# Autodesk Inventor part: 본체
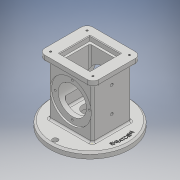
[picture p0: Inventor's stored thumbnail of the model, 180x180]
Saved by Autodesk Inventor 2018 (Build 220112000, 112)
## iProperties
Created: 2019-08
Part Number: 본체
Material: 일반
Document SubType Name: Modeling
Designer: USER
Density: 1 g/cm^3
Appearance: 기본값
Mass: 384.774 g
Surface Area: 783.555 cm^2
Volume: 384.774 cm^3
Author: USER
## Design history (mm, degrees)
sketch "스케치2"
  geometry: L1 (0, 66)-(74, 66); L2 (74, 66)-(74, 0); L3 (74, 0)-(0, 0); L4 (0, 0)-(0, 66); 1 further point
  constraints: 8 end point, 2 parallel, 1 coincident, 1 horizontal, 1 perpendicular
  dimensions: "d2" = 74 distance of L1.start L1.end; "d3" = 66 distance of L1.end L2.end
extrude "돌출1" new body sketch "스케치2" distance "d4" = 88; taper "d5" = 0 deg
node "작업 평면1"
node "작업 평면2"
sketch "스케치3"
  geometry: 1 further point
sketch "스케치4"
  geometry: L1 (0, 66)-(74, 66) reference; L2 (74, 66)-(74, 0) reference; L3 (74, 0)-(0, 0) reference; L4 (0, 0)-(0, 66) reference; C1 r 67.5 at (37, 33); 3 further points
  constraints: 2 midpoint, 1 centre point, 1 horizontal alignment, 1 vertical alignment
  dimensions: "d8" = 135 diameter of C1
extrude "돌출2" join sketch "스케치4" distance "d9" = 10; taper "d10" = 0 deg
node "작업 평면3"
sketch "스케치5"
  geometry: L1 (-9, 74)-(83, 74); L2 (83, 74)-(83, -8); L3 (83, -8)-(-9, -8); L4 (-9, -8)-(-9, 74); L5 (74, 66)-(0, 66) reference; L6 (0, 66)-(0, 0) reference; L7 (0, 0)-(74, 0) reference; L8 (74, 0)-(74, 66) reference; 5 further points
  constraints: 8 end point, 4 midpoint, 2 parallel, 1 horizontal, 1 horizontal alignment, 1 perpendicular, 1 vertical alignment
  dimensions: "d12" = 92 distance of L1.start L1.end; "d13" = 82 distance of L1.end L2.end
extrude "돌출3" join sketch "스케치5" distance "d14" = 10; taper "d15" = 0 deg
sketch "스케치6"
  geometry: L1 (-9, 74)-(83, 74) reference; L2 (-9, -8)-(-9, 74) reference; L3 (83, -8)-(-9, -8) reference; L4 (83, 74)-(83, -8) reference; L5 (11, 59)-(63, 59); L6 (63, 59)-(63, 7); L7 (63, 7)-(11, 7); L8 (11, 7)-(11, 59); 5 further points
  constraints: 8 end point, 4 midpoint, 2 parallel, 1 horizontal, 1 horizontal alignment, 1 perpendicular, 1 vertical alignment
  dimensions: "d16" = 52 distance of L5.start L5.end; "d17" = 52 distance of L5.end L6.end
extrude "돌출4" cut sketch "스케치6" distance "d18" = 8; taper "d19" = 0 deg
sketch "스케치7"
  geometry: L1 (74, 0)-(0, 0) reference; L2 (74, 0)-(74, 88) reference; L3 (0, 88)-(74, 88) reference; L4 (0, 0)-(0, 88) reference; L5 (-30.5, -10)-(104.5, -10) reference; L6 (83, 88)-(-9, 88) reference; C1 r 35 at (37, 44); 2 further points
  constraints: 1 centre point, 1 midpoint, 1 vertical alignment
  dimensions: "d20" = 70 diameter of C1; "d21" = 54 distance from line of L5 C1.centre
extrude "돌출5" cut sketch "스케치7" distance "d22" = 3; taper "d23" = 0 deg
sketch "스케치8"
  geometry: C1 r 35 at (0, 0) reference; C2 r 24 at (0, 0); 1 further point
  constraints: 1 centre point, 1 coincident
  dimensions: "d24" = 48 diameter of C2
extrude "돌출6" cut sketch "스케치8" distance "d25" = 8; taper "d26" = 0 deg
sketch "스케치9"
  geometry: C1 r 67.5 at (0, 0) reference; C2 r 25 at (0, 0); 1 further point
  constraints: 1 centre point, 1 coincident
  dimensions: "d27" = 50 diameter of C2
extrude "돌출7" cut sketch "스케치9" distance "d28" = 18; taper "d29" = 0 deg
sketch "스케치10"
  geometry: C1 r 25 at (0, 0) reference; C2 r 12.5 at (0, 0); 1 further point
  constraints: 1 centre point, 1 coincident
  dimensions: "d30" = 25 diameter of C2
extrude "돌출8" cut sketch "스케치10" distance "d31" = 10; taper "d32" = 0 deg
node "작업 평면4"
sketch "스케치11"
  geometry: L1 (15, 11)-(59, 11); L2 (59, 11)-(59, 55); L3 (59, 55)-(15, 55); L4 (15, 55)-(15, 11); L5 (11, 59)-(63, 59) reference; L6 (11, 7)-(11, 59) reference; L7 (63, 7)-(11, 7) reference; L8 (63, 59)-(63, 7) reference; L9 (11, 59)-(63, 59) reference; L10 (11, 7)-(11, 59) reference; 5 further points
  constraints: 8 end point, 4 midpoint, 2 parallel, 1 horizontal, 1 horizontal alignment, 1 perpendicular, 1 vertical alignment
  dimensions: "d34" = 44 distance of L3.end L1.start; "d35" = 44 distance of L2.end L3.end
extrude "돌출9" cut sketch "스케치11" distance "d36" = 74; taper "d37" = 0 deg
sketch "스케치12"
  geometry: C1 r 25 at (0, 0) reference; C2 r 67.5 at (0, 0) reference; 4 further points
  constraints: 2 vertical alignment, 1 horizontal alignment
  dimensions: "d38" = 59 distance of C1.centre point (0, 59); "d39" = 59 distance of point (-59, 0) C1.centre; "d40" = 59 distance of C1.centre point (0, -59)
hole "구멍1" sketch "스케치12" at (-59, 0), (0, -59), (0, 59) diameter "d41" = 9; stored, may be unused: countersink angle "d45" = 90 deg, drill point angle "d47" = 118 deg; dims "d42" = 6, "d43" = 4, "d44" = 2, "d46" = 8
sketch "스케치13"
  geometry: L1 (11, 7)-(11, 59) reference; L2 (11, 59)-(63, 59) reference; L3 (63, 59)-(63, 7) reference; L4 (63, 7)-(11, 7) reference; L5 (-9, 74)-(83, 74) reference; L6 (-9, -8)-(-9, 74) reference; L7 (83, -8)-(-9, -8) reference; L8 (83, 74)-(83, -8) reference; 5 further points
  constraints: 2 horizontal alignment, 2 vertical alignment
  dimensions: "d48" = 10 distance from line of L6 point (1, 64); "d49" = 10 distance from line of L5 point (1, 64); "d53" = 10 distance from line of L7 point (73, 2); "d54" = 10 distance from line of L8 point (73, 2)
hole "구멍2" sketch "스케치13" at (1, 64), (73, 64), (73, 2), (1, 2) diameter "d55" = 3.242; stored, may be unused: countersink angle "d59" = 90 deg, drill point angle "d61" = 118 deg; dims "d56" = 4, "d57" = 4, "d58" = 2, "d60" = 6
sketch "스케치14"
  geometry: C1 r 24 at (0, 0) reference; C2 r 35 at (0, 0) reference; 2 further points
  constraints: 1 vertical alignment
  dimensions: "d62" = 29 distance of point (0, 29) C1.centre
hole "구멍3" sketch "스케치14" at (0, 29) diameter "d63" = 3.242; stored, may be unused: countersink angle "d67" = 90 deg, drill point angle "d69" = 118 deg; dims "d64" = 4, "d65" = 4, "d66" = 2, "d68" = 6
node "작업 평면5"
sketch "스케치15"
  geometry: L1 (0, 66)-(0, 0) reference; L2 (0, 66)-(-88, 66) reference; L3 (-88, 0)-(-88, 66) reference; L4 (0, 0)-(-88, 0) reference; L5 (10, -34.5)-(10, 100.5) reference; L6 (-88, 74)-(-88, -8) reference; 4 further points
  constraints: 2 horizontal alignment, 1 midpoint
  dimensions: "d74" = 37 distance from line of L5 point (-27, 33); "d75" = 43 distance of point (-27, 33) point (-70, 33)
hole "구멍4" sketch "스케치15" at (-70, 33), (-27, 33) diameter "d76" = 4.917; stored, may be unused: countersink angle "d80" = 90 deg, drill point angle "d82" = 118 deg; dims "d77" = 12, "d78" = 4, "d79" = 2, "d81" = 17.1
fillet "모깎기1" dims "d83" = 3
fillet "모깎기2" dims "d84" = 3
fillet "모깎기3" dims "d85" = 3
sketch "스케치17"
  geometry: L1 (22, -46)-(22, -9.592) reference; L2 (-22, -46)-(22, -46) reference; L3 (-22, -46)-(-22, -9.592) reference; A1 r 24 centre (0, 0) between (-22, -9.592) and (22, -9.592) reference; 2 further points
  constraints: 1 coincident
hole "구멍5" sketch "스케치17" at (0, 0) diameter "d86" = 48; stored, may be unused: countersink angle "d90" = 90 deg, drill point angle "d92" = 118 deg; dims "d87" = 12, "d88" = 4, "d89" = 2, "d91" = 17.1
fillet "모깎기4" dims "d93" = 3
fillet "모깎기5" dims "d94" = 3
chamfer "모따기1" distance "d95" = 3; stored, may be unused: second distance "d96" = 2, angle "d97" = 45 deg
chamfer "모따기2" distance "d98" = 1; stored, may be unused: second distance "d99" = 2, angle "d100" = 45 deg
fillet "모깎기6" dims "d101" = 10
fillet "모깎기7" dims "d102" = 3
fillet "모깎기8" dims "d103" = 3
node "작업 평면6"
sketch "스케치18"
  geometry: 1 further point
sketch "스케치19"
  geometry: C1 r 4.5 at (0, -59) reference; C2 r 4.5 at (-59, 0) reference; C3 r 4.5 at (0, 59) reference; C4 r 25 at (0, 0) reference; C5 r 67.5 at (0, 0) reference; 2 further points
  constraints: 1 coincident, 1 horizontal alignment, 2 other
feature "엠보싱1" sketch "스케치19" dims "d105" = 0.5, "d106" = 0
node "솔리드1"
mirror "미러1"
pattern_circular "원형 패턴1" dims angle "d71" = 360 deg
mirror "미러2"
node "투영된 루프1"
node "투영된 루프2"
node "투영된 루프3"
node "투영된 루프4"
node "투영된 루프5"
node "투영된 루프6"
node "투영된 루프7"
node "투영된 루프8"
node "투영된 루프9"
node "투영된 루프10"
node "투영된 루프11"
node "투영된 루프12"
node "투영된 루프14"
node "투영된 루프15"
other parameters: "d6" = 0, "d11" = 98, "d33" = 33, "d73" = 33, "d104" = 37
